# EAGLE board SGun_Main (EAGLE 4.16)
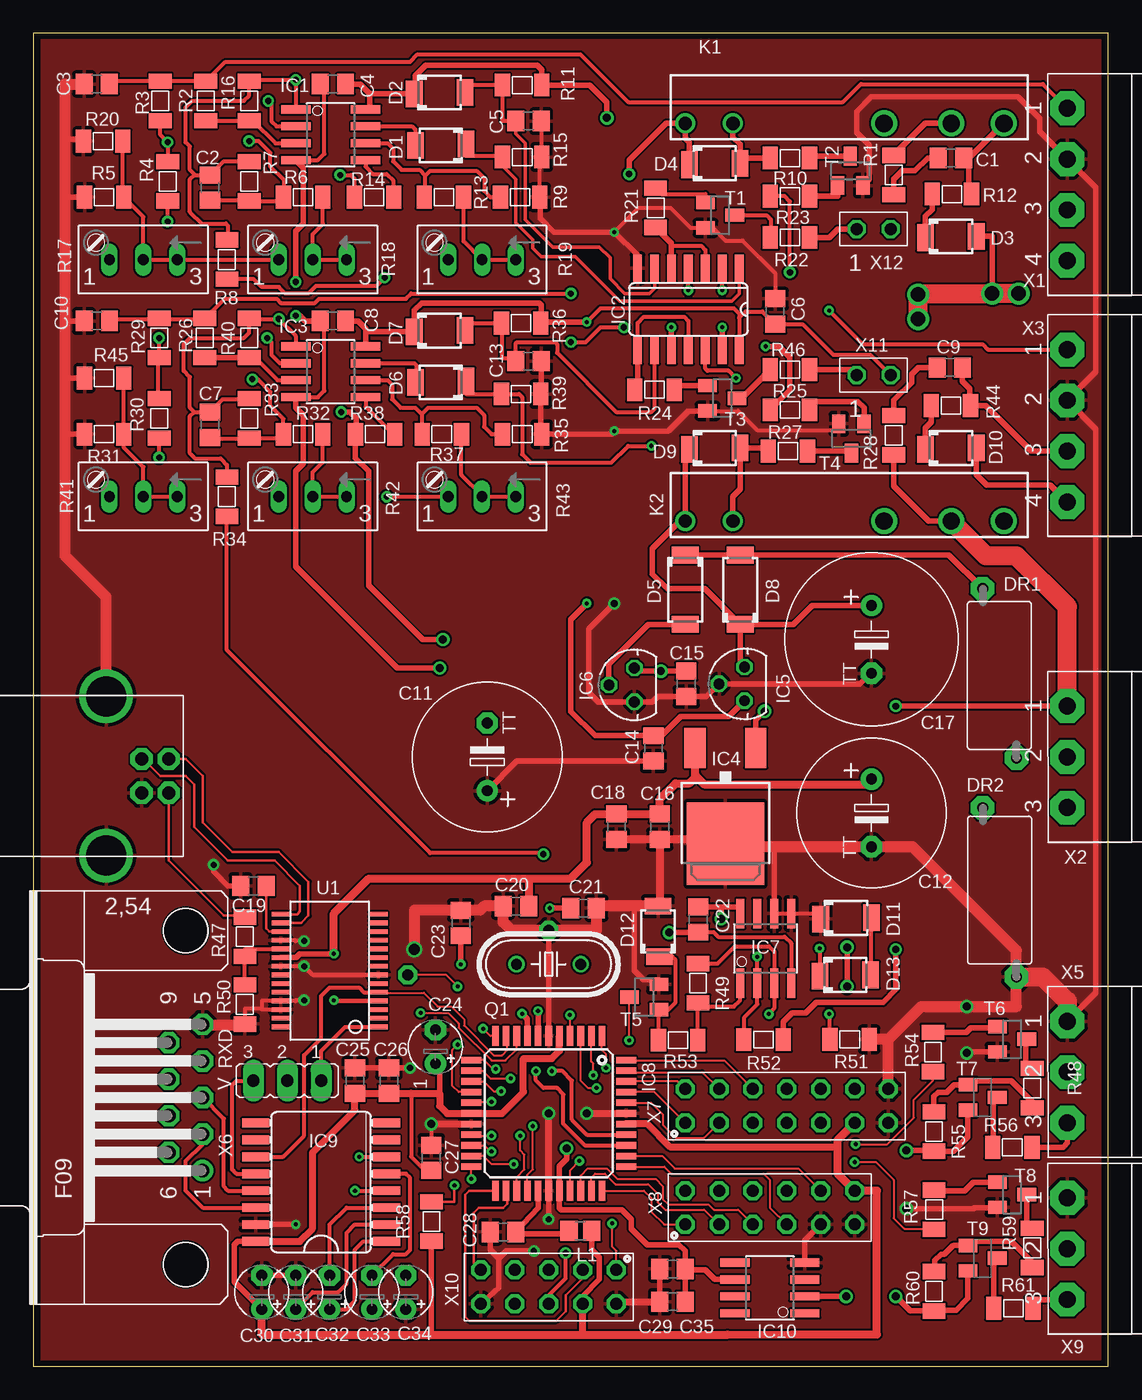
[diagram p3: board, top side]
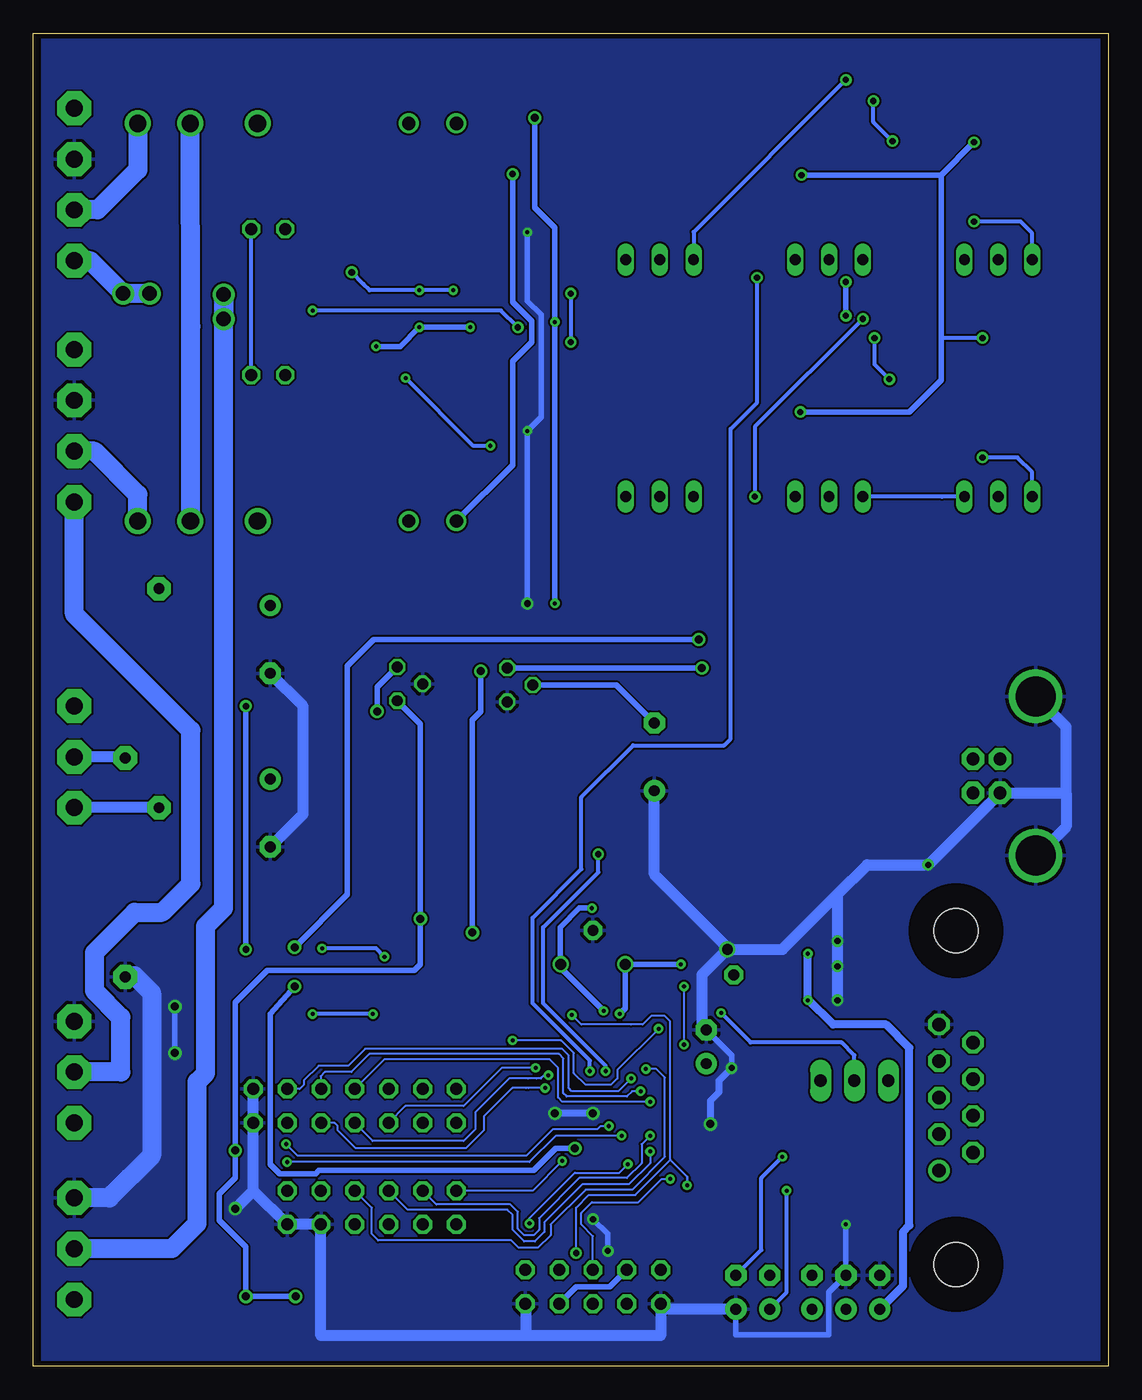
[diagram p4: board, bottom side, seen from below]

Size 80.62 x 100 mm. Coordinates in mm from the lower left corner, seen from the top.
Outline: 0,0 80.62,0 80.62,100 0,100 0,0
Copper layers (1*16): Top 0.035mm / dielectric 1.5mm / Bottom 0.035mm
Design rules "Q-PCB": minimum track width 6mil, minimum drill 0.3mm, track to track 6mil, track to pad 6mil, pad to pad 6mil, via to via 6mil, smd to smd 6mil, copper to edge 6mil, drill to drill 6mil, minimum pad ring 0.2mm, minimum via ring 0.2mm, stop-mask expansion 4mil, vias tented up to drill 0mil, thermal gap 10mil

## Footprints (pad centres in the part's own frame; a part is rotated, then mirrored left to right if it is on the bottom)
0805 = smd 1.27 x 1.524: 1 -0.953,0; 2 0.953,0
TT5D11 = drill 0.813 pad 1.6 round: + 2.54,0 | drill 0.813 pad 1.6 octagon: - -2.54,0
TT5D13 = drill 0.813 pad 1.6 round: + 2.54,0 | drill 0.813 pad 1.6 octagon: - -2.54,0
TT2D4 = drill 0.813 pad 1.6 round: + 1.27,0 | drill 0.813 pad 1.6 octagon: - -1.27,0
DIODE = smd 1.25 x 2: + -1.9,0; - 1.9,0.1
DIODE_SMD_5.0 = smd 1.25 x 2: + -2.6,0; - 2.6,0
DROSSEL1 = drill 0.813 pad 1.778 octagon: 1 -6.35,-1.27; 2 6.35,1.27
PIN1 = drill 0.813 pad 1.422 octagon: 1 0,0
SO08 = smd 0.61 x 2.21: 1 -1.905,-2.616; 2 -0.635,-2.616; 3 0.635,-2.616; 4 1.905,-2.616; 5 1.905,2.616; 6 0.635,2.616; 7 -0.635,2.616; 8 -1.905,2.616
SO14 = smd 0.66 x 2.032: 1 -3.81,-3.073; 2 -2.54,-3.073; 3 -1.27,-3.073; 4 0,-3.073; 5 1.27,-3.073; 6 2.54,-3.073; 7 3.81,-3.073; 8 3.81,3.073; 9 2.54,3.073; 10 1.27,3.073; 11 0,3.073; 12 -1.27,3.073; 13 -2.54,3.073; 14 -3.81,3.073
DPACK = smd 1.6 x 3: 1 -2.28,-4.8; 3 2.28,-4.8 | smd 5.8 x 6.2: 2 0,2.38
78LXX = drill 0.813 octagon: GND 0,1.905; IN 1.27,0; OUT -1.27,0
79LXX = drill 0.813 octagon: GND -1.27,0; IN 0,1.905; OUT 1.27,0
TQFP44 = smd 1.5 x 0.5: 1 -5.8,4; 2 -5.8,3.2; 3 -5.8,2.4; 4 -5.8,1.6; 5 -5.8,0.8; 6 -5.8,0; 7 -5.8,-0.8; 8 -5.8,-1.6; 9 -5.8,-2.4; 10 -5.8,-3.2; 11 -5.8,-4; 23 5.8,-4; 24 5.8,-3.2; 25 5.8,-2.4; 26 5.8,-1.6; 27 5.8,-0.8; 28 5.8,0; 29 5.8,0.8; 30 5.8,1.6; 31 5.8,2.4; 32 5.8,3.2; 33 5.8,4 | smd 0.5 x 1.5: 12 -4,-5.8; 13 -3.2,-5.8; 14 -2.4,-5.8; 15 -1.6,-5.8; 16 -0.8,-5.8; 17 0,-5.8; 18 0.8,-5.8; 19 1.6,-5.8; 20 2.4,-5.8; 21 3.2,-5.8; 22 4,-5.8; 34 4,5.8; 35 3.2,5.8; 36 2.4,5.8; 37 1.6,5.8; 38 0.8,5.8; 39 0,5.8; 40 -0.8,5.8; 41 -1.6,5.8; 42 -2.4,5.8; 43 -3.2,5.8; 44 -4,5.8
SO16L = smd 0.66 x 2.032: 1 -4.445,-4.902; 2 -3.175,-4.902; 3 -1.905,-4.902; 4 -0.635,-4.902; 5 0.635,-4.902; 6 1.905,-4.902; 7 3.175,-4.902; 8 4.445,-4.902; 9 4.445,4.902; 10 3.175,4.902; 11 1.905,4.902; 12 0.635,4.902; 13 -0.635,4.902; 14 -1.905,4.902; 15 -3.175,4.902; 16 -4.445,4.902
PE-FORM-D = drill 1 round: 1 -12.7,-1.2; 2 -9.12,-1.2 | drill 1.3 round: COM 7.26,-1.2; NC 2.22,-1.2; NO 11.2,-1.2
SM-0805 = smd 1.3 x 1.5: 1 -0.85,0; 2 0.85,0
HC49U-V = drill 0.813 round: 1 -2.413,0; 2 2.413,0
R-SMD-1206 = smd 1.143 x 1.702: 1 -1.473,0; 2 1.473,0
S64W = drill 0.813 long: A 2.54,1.27; E -2.54,1.27; S 0,1.27
JP3Y = drill 0.914 pad 1.587 long: 1 -2.54,0; 2 0,0; 3 2.54,0
SOT23 = smd 1 x 1.4: 1 -0.95,-1.1; 2 0.95,-1.1; 3 0,1.1
SOT23-BEC = smd 1 x 1.4: B -0.95,-1.1; C 0,1.1; E 0.95,-1.1
SSOP28DB = smd 0.348 x 1.397: 1 -4.225,-3.656; 2 -3.575,-3.656; 3 -2.925,-3.656; 4 -2.275,-3.656; 5 -1.625,-3.656; 6 -0.975,-3.656; 7 -0.325,-3.656; 8 0.325,-3.656; 9 0.975,-3.656; 10 1.625,-3.656; 11 2.275,-3.656; 12 2.925,-3.656; 13 3.575,-3.656; 14 4.225,-3.656; 15 4.225,3.656; 16 3.575,3.656; 17 2.925,3.656; 18 2.275,3.656; 19 1.625,3.656; 20 0.975,3.656; 21 0.325,3.656; 22 -0.325,3.656; 23 -0.975,3.656; 24 -1.625,3.656; 25 -2.275,3.656; 26 -2.925,3.656; 27 -3.575,3.656; 28 -4.225,3.656
G381-4 = drill 1.27 pad 2.54 octagon: 1 -5.08,-2.54; 2 -1.27,-2.54; 3 2.54,-2.54; 4 6.35,-2.54
G381-3 = drill 1.27 pad 2.54 octagon: 1 -5.08,-2.54; 2 -1.27,-2.54; 3 2.54,-2.54
USB-B = drill 0.96 pad 1.676 octagon: 1 1.27,3.81; 2 -1.27,3.81; 3 -1.27,1.778; 4 1.27,1.778 | drill 3 pad 4 round: G1 -5.969,-0.889; G2 5.969,-0.889
F09H = drill 1.016 pad 1.6 round: 1 -5.486,-1.27 | drill 1.016 pad 1.6 octagon: 2 -2.743,-1.27; 3 0,-1.27; 4 2.743,-1.27; 5 5.486,-1.27; 6 -4.115,1.27; 7 -1.372,1.27; 8 1.372,1.27; 9 4.115,1.27 | hole 3.302: -12.522,0; 12.522,0
ST14-2.54D = drill 0.9 pad 1.422 octagon: 1 -7.62,-1.27; 2 -7.62,1.27; 3 -5.08,-1.27; 4 -5.08,1.27; 5 -2.54,-1.27; 6 -2.54,1.27; 7 0,-1.27; 8 0,1.27; 9 2.54,-1.27; 10 2.54,1.27; 11 5.08,-1.27; 12 5.08,1.27; 13 7.62,-1.27; 14 7.62,1.27
ST12-2.54D = drill 0.9 pad 1.422 octagon: 1 -6.35,-1.27; 2 -6.35,1.27; 3 -3.81,-1.27; 4 -3.81,1.27; 5 -1.27,-1.27; 6 -1.27,1.27; 7 1.27,-1.27; 8 1.27,1.27; 9 3.81,-1.27; 10 3.81,1.27; 11 6.35,-1.27; 12 6.35,1.27
ST10-2.54D = drill 0.9 pad 1.422 octagon: 1 -5.08,-1.27; 2 -5.08,1.27; 3 -2.54,-1.27; 4 -2.54,1.27; 5 0,-1.27; 6 0,1.27; 7 2.54,-1.27; 8 2.54,1.27; 9 5.08,-1.27; 10 5.08,1.27
ST2-254 = drill 0.9 octagon: 1 -1.27,0; 2 1.27,0

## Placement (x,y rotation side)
C1  100n  [0805]  68.81,90.64 180 top
C2  100n  [0805]  13.25,88.42 90 top
C3  100n  [0805]  4.76,96.2 180 top
C4  100n  [0805]  22.46,96.2 180 top
C5  220n  [0805]  37.14,93.42 180 top
C6  10n  [0805]  55.64,79.13 90 top
C7  100n  [0805]  13.25,70.64 90 top
C8  100n  [0805]  22.46,78.42 180 top
C9  100n  [0805]  68.73,74.92 180 top
C10  100n  [0805]  4.76,78.42 180 top
C11  220u  [TT5D11]  34.05,45.71 270 top
C12  220u  [TT5D11]  62.86,41.51 90 top
C13  220n  [0805]  37.14,75.4 180 top
C14  100n  [0805]  46.51,46.35 90 top
C15  100n  [0805]  48.97,51.19 270 top
C16  100n  [0805]  46.98,40.47 90 top
C17  470u  [TT5D13]  62.86,54.52 90 top
C18  22p  [0805]  43.73,40.47 90 top
C19  100n  [0805]  16.5,36.03 180 top
C20  100n  [0805]  36.19,34.52 0 top
C21  22pF  [0805]  41.27,34.36 180 top
C22  100n  [0805]  49.87,33.52 270 top
C23  22pF  [0805]  32.06,33.25 270 top
C24  1uF  [TT2D4]  30.16,23.96 270 top
C25  100n  [0805]  24.12,21.42 90 top
C26  100n  [0805]  26.66,21.42 90 top
C27  100n  [0805]  29.84,15.63 270 top
C28  100n  [0805]  35.24,10.07 180 top
C29  100n  [0805]  47.94,7.3 0 top
C30  1uF  [TT2D4]  17.14,5.55 270 top
C31  1uF  [TT2D4]  19.68,5.55 270 top
C32  1uF  [TT2D4]  22.22,5.55 270 top
C33  1uF  [TT2D4]  25.39,5.55 270 top
C34  1uF  [TT2D4]  27.93,5.55 270 top
C35  100n  [0805]  47.94,4.84 0 top
D1  1N4148  [DIODE]  30.55,91.59 0 top
D2  1N4148  [DIODE]  30.47,95.56 180 top
D3  1N4148  [DIODE]  68.81,84.77 180 top
D4  BAV103  [DIODE]  51.11,90.24 180 top
D5  1N4002  [DIODE_SMD_5.0]  48.89,58.26 90 top
D6  1N4148  [DIODE]  30.55,73.81 0 top
D7  1N4148  [DIODE]  30.47,77.7 180 top
D8  1N4002  [DIODE_SMD_5.0]  53.02,58.26 270 top
D9  BAV103  [DIODE]  51.11,68.89 180 top
D10  1N4148  [DIODE]  68.81,68.89 180 top
D11  ZF4,3  [DIODE]  60.96,33.64 180 top
D12  1N4148  [DIODE]  46.85,32.62 270 top
D13  ZF4,3  [DIODE]  60.9,29.36 180 top
DR1  [DROSSEL1]  72.46,51.98 90 top
DR2  [DROSSEL1]  72.46,35.55 270 top
E1  0VQuarz  [PIN1]  38.65,32.7 0 top
E2  Messpkt.  [PIN1]  28.09,29.36 0 top
IC1  LM358  [SO08]  22.3,92.39 270 top
IC2  4093D  [SO14]  49.13,79.29 180 top
IC3  LM358  [SO08]  22.3,74.61 270 top
IC4  7805  [DPACK]  51.91,41.59 180 top
IC5  78L09  [78LXX]  53.34,51.19 90 top
IC6  79L09  [79LXX]  45.08,51.11 90 top
IC7  LM358  [SO08]  54.93,31.34 0 top
IC8  MEGA16-A  [TQFP44]  38.65,18.96 270 top
IC9  MAX232ECWE  [SO16L]  21.58,13.81 90 top
IC10  [SO08]  55.24,5.87 90 top
K1  RELAIS  [PE-FORM-D]  61.59,94.45 0 top
K2  RELAIS  [PE-FORM-D]  61.59,64.6 0 top
L1  10uH  [SM-0805]  41.03,10.15 180 top
Q1  16MHz  [HC49U-V]  38.65,30.16 180 top
R1  100R  [R-SMD-1206]  64.53,89.37 270 top
R2  10K  [R-SMD-1206]  12.93,94.93 90 top
R3  1K5  [R-SMD-1206]  9.52,94.93 90 top
R4  10K  [R-SMD-1206]  10.08,88.89 270 top
R5  4K75  [R-SMD-1206]  5.31,87.7 180 top
R6  6K81  [R-SMD-1206]  20.24,87.7 0 top
R7  511K  [R-SMD-1206]  16.19,88.89 270 top
R8  10K  [R-SMD-1206]  14.52,83.02 90 top
R9  100K  [R-SMD-1206]  36.51,87.7 0 top
R10  330R  [R-SMD-1206]  56.75,90.64 180 top
R11  100K  [R-SMD-1206]  36.67,96.12 180 top
R12  4K75  [R-SMD-1206]  68.89,87.94 0 top
R13  10K  [R-SMD-1206]  30.79,87.7 180 top
R14  10K  [R-SMD-1206]  25.55,87.7 0 top
R15  100K  [R-SMD-1206]  36.67,90.72 0 top
R16  10K  [R-SMD-1206]  16.19,94.93 270 top
R17  1K  [S64W]  8.25,84.29 180 top
R18  2K  [S64W]  20.95,84.29 180 top
R19  10K  [S64W]  33.65,84.29 180 top
R20  200R  [R-SMD-1206]  5.23,91.91 180 top
R21  22K1  [R-SMD-1206]  46.67,86.91 270 top
R22  680R  [R-SMD-1206]  56.75,84.69 180 top
R23  10K  [R-SMD-1206]  56.75,87.78 0 top
R24  22K1  [R-SMD-1206]  46.59,73.26 180 top
R25  10K  [R-SMD-1206]  56.75,71.75 0 top
R26  10K  [R-SMD-1206]  12.85,77.15 90 top
R27  330R  [R-SMD-1206]  56.59,68.65 180 top
R28  100R  [R-SMD-1206]  64.53,69.84 90 top
R29  1K5  [R-SMD-1206]  9.44,77.15 90 top
R30  10K  [R-SMD-1206]  9.44,71.11 270 top
R31  4K75  [R-SMD-1206]  5.31,69.92 180 top
R32  6K81  [R-SMD-1206]  20.24,69.92 0 top
R33  511K  [R-SMD-1206]  16.19,71.11 270 top
R34  10K  [R-SMD-1206]  14.52,65.24 90 top
R35  100K  [R-SMD-1206]  36.67,69.92 0 top
R36  100K  [R-SMD-1206]  36.59,78.26 180 top
R37  10K  [R-SMD-1206]  30.63,69.92 180 top
R38  10K  [R-SMD-1206]  25.63,69.92 0 top
R39  100K  [R-SMD-1206]  36.59,72.94 0 top
R40  10K  [R-SMD-1206]  16.19,77.15 270 top
R41  1K  [S64W]  8.25,66.51 180 top
R42  2K  [S64W]  20.95,66.51 180 top
R43  10K  [S64W]  33.65,66.51 180 top
R44  4K75  [R-SMD-1206]  68.81,72.07 0 top
R45  200R  [R-SMD-1206]  5.31,74.13 180 top
R46  680R  [R-SMD-1206]  56.75,74.77 180 top
R47  4K7  [R-SMD-1206]  15.87,32.22 90 top
R48  15K  [R-SMD-1206]  74.91,20.86 270 top
R49  100K  [R-SMD-1206]  49.85,28.73 270 top
R50  10K  [R-SMD-1206]  15.87,27.14 270 top
R51  1K  [R-SMD-1206]  61.23,24.52 0 top
R52  1K5  [R-SMD-1206]  54.76,24.5 180 top
R53  47K  [R-SMD-1206]  48.36,24.46 180 top
R54  100K  [R-SMD-1206]  67.47,23.57 90 top
R55  47K  [R-SMD-1206]  67.55,17.6 270 top
R56  360R  [R-SMD-1206]  73.42,16.41 0 top
R57  100K  [R-SMD-1206]  67.55,11.75 90 top
R58  10K  [R-SMD-1206]  29.86,10.86 90 top
R59  15K  [R-SMD-1206]  74.91,8.88 270 top
R60  47K  [R-SMD-1206]  67.55,5.62 270 top
R61  360R  [R-SMD-1206]  73.5,4.35 0 top
RXD  JP1  [JP3Y]  19.04,21.42 180 top
T1  BC846  [SOT23]  51.51,86.35 270 top
T2  BC846  [SOT23]  61.27,89.69 0 top
T3  BC846  [SOT23]  51.67,72.62 270 top
T4  BC846  [SOT23]  61.35,69.61 180 top
T5  BC846  [SOT23]  45.82,27.69 90 top
T6  BC846  [SOT23]  73.41,24.53 270 top
T7  BC856  [SOT23-BEC]  71.19,20.17 270 top
T8  BC846  [SOT23]  73.41,12.86 270 top
T9  BC856  [SOT23-BEC]  71.19,8.1 270 top
U1  [SSOP28DB]  22.22,29.68 90 top
X1  [G381-4]  80.08,89.29 270 top
X2  G381-3  [G381-3]  80.08,44.44 270 top
X3  [G381-4]  80.08,71.19 270 top
X4  USB-B  [USB-B]  6.34,44.28 270 top
X5  G381-3  [G381-3]  80.09,20.8 270 top
X6  F09H  [F09H]  11.42,20.15 90 top
X7  [ST14-2.54D]  56.51,19.52 0 top
X8  [ST12-2.54D]  55.24,11.9 0 top
X9  G381-3  [G381-3]  80.09,7.54 270 top
X10  ST10-2.54D  [ST10-2.54D]  38.65,5.95 180 top
X11  ST2-254  [ST2-254]  63.02,74.37 0 top
X12  ST2-254  [ST2-254]  63.02,85.32 0 top

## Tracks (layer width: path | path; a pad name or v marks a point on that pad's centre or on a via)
0_DETEC  (via drill 0.3)
  Top 0.152: IC8.11 34.28,24.76 v33.73,25.31 | T5.3 44.69,27.69 44.68,27.7 v44.68,24.44
  Bottom 0.152: v33.73,25.31 36.82,22.22 36.82,21.58 37.3,21.11 39.21,21.11 40.08,21.98 40.08,23.49 41.03,24.44 v44.68,24.44
+5V  (via drill 0.46, 0.6)
  Top 0.305: R3.1 9.52,92.39 v10.08,91.83 10.08,90.4 10.07,90.4 R4.1 | R14.1 24.08,89.1 23.81,89.37 v23.01,89.37 | v9.44,77.15 R29.1 9.36,75.59 9.36,72.54 9.39,72.54 R30.1
  Top 0.406: IC8.29 39.45,11.89 39.6,11.74 44.13,11.74 44.84,11.03 44.84,10.31 46.03,9.12 48.41,9.12 48.89,8.65 C29.2 48.89,7.22 | C35.2 48.89,7.22 | IC10.6 51.11,6.5 50.4,7.22 48.89,7.22 | 39.44,13.17 39.44,15 40,15.55 v40,16.34 | v61.03,28.49 v61.03,31.43 | v23.09,71.59 23.73,71.59 24.2,71.11 24.2,69.92 R38.1 24.16,68.14 25.16,67.14 25.16,58.57 29.2,54.52 v30.71,54.52
  Top 0.508: IC8.29 39.44,13.17
  Bottom 0.305: v9.44,77.15 12.54,77.15 | 12.54,89.37
  Bottom 0.406: v40,16.34 41.43,16.34 43.1,14.68 59.21,14.68 59.45,14.44 62.15,14.44 62.86,15.15 62.86,25.23 | v61.03,31.43 57.07,35.39 57.07,52.54 55.08,54.52 v30.71,54.52 | 62.86,25.23 | v61.03,28.49 62.86,26.43 62.86,25.23 | 12.54,89.37 v23.01,89.37 | 12.54,89.37 v10.08,91.83 | v23.09,71.59 14.92,71.59 12.54,73.97 12.54,77.15 12.54,89.37
+9V  (via drill 0.3, 0.6)
  Top 0.305: IC7.8 53.02,34.47 | 70.08,7.14 T9.E | 52.94,78.65 52.94,78.97 52.54,79.37 42.78,79.37 42.54,79.37 v41.51,78.34 | 52.94,78.65 IC2.14 | 52.94,78.65 53.41,79.13 54.68,79.13 C6.1 | C6.1 | C6.1 | C6.1 57.7,78.18 60,75.88 62.78,75.88 X11.2 | X11.2 | X11.2 | 28.57,95.48 D2.- | 25.24,94.61 IC1.8
  Top 0.406: 51.59,34.47 C22.1 | 51.59,34.47 53.02,34.47 | IC10.2 v60.95,5.23 | R60.2 65.77,4.15 v64.69,5.23 | T9.E 70.09,5.08 69.21,4.2 67.7,4.2 | R55.2 69,16.13 70.08,17.22 70.08,19.28 70.09,19.28 T7.E | v65.48,16.19 67.46,16.19 | v51.59,33.57 51.59,34.47 | IC5.OUT 52.14,48.73 48.57,48.73 47.14,47.3 C14.2 42.14,47.3 40.32,49.13 40.32,56.03 v41.51,57.22 | C4.1 24.52,96.2 25.24,95.48 | 28.57,95.48 25.24,95.48 | 25.24,95.48 25.24,94.61 | v43.02,93.66 43.02,94.85 41.75,96.12 R11.1 38.14,97.26 37.78,97.62 29.44,97.62 28.65,96.83 28.65,95.54 D2.- | C8.1 24.36,78.42 24.92,77.86 24.92,77.62 | IC3.8 | IC3.8 | 24.92,77.62 IC3.8 | 24.92,77.62 24.94,77.6 D7.- 28.57,79.22 29.13,79.77 37.94,79.77 38.09,79.61 38.09,78.42 38.17,78.34 | 38.17,78.34 38.09,78.26 R36.1 | v41.51,78.34 38.17,78.34
  Top 0.508: R60.2 67.6,4.15 67.62,4.12 67.7,4.2 | R55.2 67.55,16.11 67.54,16.11 67.46,16.19 | IC10.2
  Bottom 0.305: X11.2 | X11.2 | X11.2 X12.2 | X11.2
  Bottom 0.406: v60.95,5.23 v64.69,5.23 64.69,8.96 66.67,10.95 66.67,12.93 65.48,14.12 v65.48,16.19 65.48,27.3 63.1,29.68 52.06,29.68 51.59,30.16 v51.59,33.57 51.59,48.17 IC5.OUT | v41.51,57.22 v41.51,78.34 41.51,85.4 43.02,86.91 v43.02,93.66
+LON1
  Top 0.406: R12.1 67.42,86.78 66.91,86.27 66.91,84.77 66.91,84.76 D3.-
+LON2
  Top 0.406: R44.1 67.34,70.83 66.91,70.4 66.91,68.89 D10.-
-9V  (via drill 0.46, 0.6)
  Top 0.305: C22.2 51.01,32.56 51.35,32.22 56.35,32.22 56.83,31.74 56.83,28.81 56.83,28.8 IC7.4 | C4.2 21.82,95.88 21.82,90.96 21.35,90.48 IC1.4 | IC1.4 19.6,90.48 | IC1.4 | C8.2 21.82,78.42 21.82,73.18 21.35,72.7 IC3.4 | IC3.4 | IC3.4
  Top 0.406: C22.2 49.84,32.54 v47.7,32.54 | C15.1 | C15.1 v47.06,52.14 45.32,52.14 IC6.OUT | IC1.4 20.24,89.93 20.24,85.72 19.68,85.16 v19.68,81.35 | IC1.4 | v19.68,78.81 20,78.81 20.39,78.42 C8.2 | IC3.4 19.68,71.91 20.24,71.35 20.24,67.7 19.68,67.14 19.68,60 27.3,52.38 28.89,52.38 | v30.47,52.38 28.89,52.38 | 28.89,52.38
  Bottom 0.406: v47.7,32.54 47.7,48.49 47.06,49.13 v47.06,52.14 | IC6.OUT v30.47,52.38 | v30.47,52.38 | v19.68,78.81 v19.68,81.35
-LON1  (via drill 1.1)
  Top 0.406: D3.+ 71.91,84.77 v71.91,80.48
  Top 1.422: v71.91,80.48 | v73.89,80.48 v71.91,80.48 | v66.35,78.58 66.35,80.48 v71.91,80.48
  Bottom 1.422: X9.2 70.24,8.81 68.34,10.71 68.34,21.35 67.7,21.98 67.7,33.01 66.35,34.36 v66.35,80.4 | X1.4 76.35,82.94 v73.89,80.48 v71.91,80.48 | v66.35,80.4 66.35,80.48 | v66.35,80.4 v66.35,78.58
-LON2
  Top 0.406: D10.+ 70.71,66.91 71.51,66.11 76.27,66.11 X3.4
  Bottom 1.422: X5.2 74.05,22.07 74.05,26.19 76.04,28.17 76.04,31.03 | X3.4 77.54,56.43 68.81,47.7 68.81,36.19 70.96,34.05 73.02,34.05 76.04,31.03 | 76.04,31.03
/RESET  (via drill 0.3, 0.46)
  Top 0.152: IC8.4 40.24,24.76 v40.24,26.35
  Top 0.203: R58.2 31.59,12.33 v31.59,13.57
  Top 0.305: X10.6 38.65,5.31 39.92,6.58 v39.92,8.49
  Bottom 0.152: v39.92,8.49 39.92,11.9 38.97,12.85 35.48,12.85 33.89,14.44 | 33.89,14.44 | 33.89,14.44 32.86,15.47 32.86,18.57 | 32.86,18.57 | 32.86,18.57 32.86,25.87 33.25,26.27 34.28,26.27 34.92,25.63 35.79,25.63 39.52,25.63 v40.24,26.35
  Bottom 0.203: v31.59,13.57 31.59,14.2 32.86,15.47
D0
  Top 0.152: IC8.40 46.34,19.76 47.22,18.88 47.22,18.09 48.18,17.14 50.32,17.14 X7.3 | X7.3 | X7.3
D1
  Top 0.152: X7.1 | X7.1 | IC8.41 46.58,20.56 X7.1
D2
  Top 0.152: X7.2 | X7.2 | IC8.42 48.32,21.36 X7.2
D3
  Top 0.152: 44.48,22.14 IC8.43 44.45,22.13 44.52,22.06 50.16,22.06 X7.4 | X7.4 | X7.4
D4
  Top 0.152: IC8.44 44.48,22.93 51.83,22.93 X7.6 | X7.6 | X7.6
D5  (via drill 0.3)
  Top 0.152: IC8.1 42.65,24.68 42.55,24.68 42.55,24.43 42.62,24.36 42.62,23.73 42.95,23.4 v42.95,22.38
  Bottom 0.152: v42.95,22.38 45.49,22.38 48.35,19.53 52.72,19.53 53.99,18.26 X7.5
D6  (via drill 0.3)
  Top 0.152: IC8.2 41.84,22.86 42,22.7 v42,21.83
  Bottom 0.152: v42,21.83 42.31,21.83 42.55,21.59 42.87,21.59 43.51,21.59 44.94,21.59 47.48,19.05 47.48,17.78 48.35,16.91 55.18,16.91 56.52,18.25 | 56.52,18.25 56.53,18.26 | 56.52,18.25 X7.7
D7  (via drill 0.3)
  Top 0.152: IC8.3 41.05,21.41 41.59,20.87 42.22,20.87 42.23,20.88 v42.23,20.88
  Bottom 0.152: v42.23,20.88 43.51,20.88 43.66,20.88 44.7,20.88 46.84,18.73 46.84,17.7 48.19,16.35 56.45,16.35 57.8,17.7 57.8,18.02 58.04,18.26 58.9,18.26 | 58.9,18.26 58.91,18.26 | 58.9,18.26 X7.9
EN1  (via drill 0.3)
  Top 0.152: IC8.16 32.92,19.84 v34.36,19.84
  Bottom 0.152: v34.36,19.84 35.4,19.84 36.03,19.84 40.79,19.84 40.95,19.84 41.27,20.15 41.27,22.38 41.91,23.02 54.3,23.02 56.53,20.8 X7.8
EN2  (via drill 0.3)
  Top 0.152: IC8.15 31.89,20.56 31.43,21.03 31.43,23.73 v31.82,24.12 | E2.1 30.95,29.36 v31.82,28.49
  Bottom 0.152: v31.82,24.12 v31.82,28.49
GND  (via drill 0.3, 0.46, 0.5, 0.6, 0.8)
  Top 0.203: C19.2 15.55,35.39 | U1.18 18.46,31.95 | 18.67,27.4 18.73,27.46 | 18.73,30 18.72,30 U1.21
  Top 0.305: 18.67,27.4 19.68,27.4 19.68,27.46 v20.31,27.46 | 18.67,27.4 U1.25 | 18.72,30 19.68,30 v20.31,30 | U1.18 19.63,31.95 19.68,31.9 v20.31,31.9 | 18.67,27.4 17.14,27.4 17.14,26.82 | 15.87,25.55 R50.2 15.87,26.82 17.14,26.82 | U1.26 17.14,26.75 17.14,26.82 | 29.84,18.25 | v29.84,18.17 29.84,18.25 | 29.84,18.25 C27.1 | 29.84,18.25 | IC7.5 59.05,33.96 D11.- | IC7.6 IC7.5 | IC7.5 | D11.- 59.05,33.49 | D11.- | T3.2 52.86,71.67 54.29,70.24 60.32,70.24 60.32,70.71 | 60.32,70.71 60.32,70.72 | 60.32,70.71 T4.2 | v43.57,85.08 45.4,86.91 47.78,86.91 49.28,85.4 T1.2 50.95,85.4 51.91,84.45 53.18,84.45 55.64,81.99 55.64,80.16 | 45.32,83.34 IC2.7 | 55.64,80.16 | 55.64,80.16 C6.2 | 3.8,92.07 3.76,92.02 R20.2 | 3.8,92.07 | R5.2 3.84,87.66 3.8,87.62 3.76,87.67 | 38.09,90.72 | 38.09,90.72 R15.2 38.14,93.37 C5.1 | R9.2 37.98,90.61 38.09,90.72 | C5.1
  Top 0.356: U1.7 23.81,29.36 20.95,29.36 v20.31,30
  Top 0.406: v19.68,10.63 IC9.15 | C30.- C31.- | C25.2 C26.2 v28.25,22.38 | v13.52,37.62 13.52,37.11 14.6,36.03 C19.2 | X10.10 34.92,5.87 34.92,8.09 | v38.65,11.03 38.65,13.09 | v37.54,8.65 37.06,8.65 36.35,8.65 35.48,8.65 34.92,8.09 | C28.2 34.28,8.73 34.92,8.09 | X8.9 | IC10.4 57.86,9.44 X8.9 | C35.1 | C35.1 | C35.1 C29.1 | 38.66,32.7 38.66,32.71 | 38.66,32.7 E1.1 | IC8.6 38.66,24.76 38.66,32.7 | D12.+ 45.08,34.52 45.08,29.68 45.79,28.97 46.91,28.97 46.91,28.66 T5.2 | v65.48,11.82 70.48,11.82 70.56,11.9 | T8.2 70.56,11.9 | 70.56,11.9 | T6.2 70.1,23.58 v70,23.49 | IC7.6 55.56,38.97 | C15.2 | C15.2 46.83,50.24 46.43,49.84 IC6.GND | C15.2 50.48,50.24 IC5.GND 61.99,51.19 62.86,52.06 C17.- | X5.1 79.69,28.01 79.69,70.32 X3.2 79.69,74.61 79.69,88.42 X1.2 | 55.56,38.97 | C11.+ | C14.1 36.27,45.4 C11.+ | IC6.GND | IC6.GND | IC6.GND 42.38,49.84 41.67,50.56 41.67,55.32 v43.57,57.22 | v43.57,57.22 | T2.2 62.7,89.07 62.7,91.59 61.75,92.55 61.75,94.13 62.86,95.24 73.81,95.24 75.48,93.58 75.48,92.62 X1.2 | X1.2 | X1.2 | T3.2 49.13,71.67 47.62,70.16 v43.57,70.16 43.33,69.92 R35.2 38.17,69.92 | v43.57,85.08 45.32,83.34 | v43.57,85.08 | v43.57,85.08 41.59,85.08 39.05,85.08 38.02,86.12 | 38.02,86.12 | R9.2 37.98,87.66 38.02,87.62 38.02,86.12 | 38.09,72.94 | 38.09,72.94 R39.2 38.06,70.04 38.17,69.92 | 38.09,72.94 C13.1 | 38.17,69.92 | 2.38,92.07 3.8,92.07 | 2.38,87.7 R5.2 | C10.2 2.38,78.42 | R45.2 2.38,74.13 | R31.2 2.38,69.92
  Top 0.508: 38.65,13.09 IC8.28 v38.65,18.96 | v29.84,18.17 IC8.18 32.86,18.16 | v41.51,18.96 IC8.39 | X10.2 43.89,4.84 C35.1
  Top 0.61: C18.1 C16.1 | IC4.2 | IC4.2 | C16.1 51.91,39.52 IC4.2 | C16.1 | D12.+ 46.98,34.52 C16.1 | IC4.2 51.99,39.21 51.99,38.97
  Top 0.813: X6.5 12.69,25.55 15.76,25.55 R50.2 | v28.57,31.27 28.57,34.2 C23.1 33.49,34.2 33.81,34.52 35.16,34.52 | 35.16,34.52 | 35.16,34.52 C20.1 35.24,33.33 35.87,32.7 E1.1 | 38.66,32.7 42.22,32.7 C21.1 42.38,34.52 D12.+ | X7.14 | 64.13,24.52 R51.2 | X7.14 64.13,24.52 | 64.13,24.52 66.59,26.98 v70,26.98 73.73,26.98 DR2.2 73.73,31.19 65.96,38.97 C12.- 55.72,38.97 55.56,38.97 54.52,38.97 51.99,38.97 | X4.G1 5.46,57.71 2.38,60.8 2.38,69.92 2.38,74.13 2.38,78.42 2.38,87.7 2.38,92.07 2.38,96.2 C3.2 | C3.2 | C3.2
  Top 1.422: DR2.2 75.72,29.2 77.55,27.37 77.54,27.37 | 77.54,27.37 77.54,27.38 | X5.1 77.54,27.37
  Bottom 0.406: v19.68,10.63 C31.- 20.95,5.55 20.95,2.38 27.93,2.38 C34.+ | C24.- 28.25,23.33 v28.25,22.38 | v37.54,8.65 37.54,9.92 v38.65,11.03 | v70,26.98 v70,23.49 | v43.57,85.08 43.57,79.92 42.54,78.89 42.54,71.19 v43.57,70.16 v43.57,57.22
  Bottom 0.508: v29.84,18.17 29.84,19.92 29.2,20.55 29.2,21.42 v28.25,22.38 | v38.65,18.96 v41.51,18.96
  Bottom 0.813: X4.G1 3.17,47.97 3.17,43.02 | 3.17,43.02 3.17,40.48 5.33,38.32 X4.G2 | 3.17,43.02 X4.4 v13.52,37.62 18.09,37.62 20.31,35.39 | v20.31,27.46 v20.31,30 v20.31,31.9 20.31,35.39 | 20.31,35.39 24.44,31.27 v28.57,31.27 | v28.57,31.27 30.47,29.36 30.47,25.23 C24.- | C34.+ 33.57,4.28 X10.10 33.57,2.3 43.65,2.3 | X10.2 43.65,4.68 43.65,2.3 | 43.65,2.3 59.05,2.3 X8.9 | X7.13 | X7.13 X7.14 | X7.13 | X8.11 | 64.13,13.17 X7.13 | X8.11 64.13,13.17 | X8.9 | X8.11 | X8.9 X8.11 | X8.11 | 64.13,13.17 v65.48,11.82 | C17.- 60.4,49.52 60.4,41.43 C12.- | v28.57,31.27 28.49,31.35 34.05,36.9 C11.+
  Bottom 1.422: X9.1 74.92,12.62 71.75,15.79 71.75,28.01 73.02,29.28 73.73,29.28 DR2.2
  pour Bottom: 0.63,99.53 80,99.53 80,0.47 0.63,0.47
  pour Top: 0.63,99.53 80,99.53 80,0.47 0.63,0.47
IC8
  Top 0.305: IC2.5 47.86,84.05 50.08,84.05 50.4,83.73 50.4,82.39 | 50.4,82.39 | 50.4,82.39 IC2.3
  Top 0.406: IC2.5 | R21.2 47.86,84.25 IC2.5
N$1  (via drill 0.3)
  Top 0.305: R52.2 53.29,24.55 53.33,24.6 53.33,26.19 54.29,27.15 IC7.2 v54.29,30.71 | D13.- 59,31.32 v58.97,31.35
  Bottom 0.305: v58.97,31.35 54.92,31.35 v54.29,30.71
N$2
  Top 0.203: U1.16 20.08,33.25 20.63,33.81 20.63,36.35 18.41,38.57 14.92,38.57 12.69,40.79 12.69,44.28 11.42,45.55 X4.2
N$3
  Top 0.305: D13.+ 62.78,29.36 62.86,29.44 D11.+
N$4  (via drill 0.3)
  Top 0.305: R49.1 51.32,30.21 52.62,31.51 55.16,31.51 55.56,31.11 IC7.3 55.56,26.83 v55.16,26.43 | R51.1 59.75,24.53 59.68,24.6 v59.68,26.43
  Bottom 0.305: v55.16,26.43 v59.68,26.43
N$5
  Top 0.305: 49.88,27.26 49.92,27.3 | 49.88,27.26 R49.2 50.13,26.98 52.54,26.98 53.02,27.46 IC7.1 | R53.1 49.83,27.21 49.88,27.26
N$6
  Top 0.203: X4.3 8.25,45.55 9.52,44.28 11.42,44.28 12.06,43.65 12.06,40.48 14.6,37.94 18.09,37.94 20,36.03 20,34.12 19.78,33.91 U1.15 18.63,33.91
N$7
  Top 0.305: IC9.1 24.76,9.36 24.12,8.73 24.12,4.92 23.49,4.28 C32.+
N$8  (via drill 0.3)
  Top 0.305: v24.12,13.17 IC9.4
  Bottom 0.305: v24.12,13.17 24.12,5.55 C33.+
N$9
  Top 0.305: IC9.3 23.49,11.9 22.22,10.63 C32.-
N$10
  Top 0.305: IC9.5 27.93,14.44 28.25,14.12 28.25,8.73 27.93,8.41 26.98,8.41 C33.-
N$11
  Top 0.305: IC9.2 24.12,10.63 23.49,10 23.49,6.18 22.85,5.55 20.95,5.55 C31.+
N$12  (via drill 0.3)
  Top 0.305: v24.44,15.71 IC9.6
  Bottom 0.305: C34.- 26.03,8.73 26.03,14.12 v24.44,15.71
N$13
  Top 0.406: X12.1 60.32,85.32 59.68,84.69 58.18,84.69 | 58.18,84.69 | R22.1 58.18,84.69
N$14
  Top 0.203: C19.1 17.46,32.85 17.71,32.6 U1.17
  Top 0.305: U1.17 18.66,32.6
N$15  (via drill 0.3)
  Top 0.152: IC8.9 36.25,23.79 35.4,22.93 34.36,22.93 31.9,25.39 31.9,25.71 31.11,26.5 v29.05,26.5
  Bottom 0.305: RXD.2 19.04,23.33 20,24.28 26.82,24.28 v29.05,26.5
N$16
  Top 0.305: X6.2 12.69,16.66 11.42,15.39 11.42,13.17 12.69,11.9 IC9.14
N$17
  Top 0.305: X6.3 14.28,18.57 14.28,13.49 14.6,13.17 IC9.13
N$18
  Top 0.305: R13.1 32.27,84.4 R19.S | R19.S | R19.S R19.E | R19.S
N$19
  Top 0.406: C28.1 | IC8.27 37.85,11.89 C28.1 | C28.1 36.11,9.92 40.18,9.92 L1.2
N$20
  Bottom 0.813: DR1.1 | X2.2 73.81,45.71 DR1.1
N$21
  Bottom 0.813: DR2.1 71.19,41.82 71.27,41.9 X2.3
N$22
  Top 0.406: DR1.2 68.65,60.87 53.02,60.87 | 48.89,60.87 53,60.87
  Top 0.61: 53.02,60.87 D8.+ 53,60.87 | D5.- 48.89,60.87 | D5.-
N$23
  Top 0.305: R50.1 15.87,30.63 | U1.19 15.91,31.3 15.87,31.27 15.87,30.63 | 15.87,30.63 R47.1
N$24
  Top 0.406: R46.1 | X11.1 61.35,74.77 R46.1
N$25  (via drill 0.3)
  Top 0.406: IC8.7 v37.85,26.66 | v38.73,34.36 C21.2
  Bottom 0.406: v37.85,26.66 41.06,29.87 Q1.1 41.11,30.2 41.11,32.93 39.68,34.36 v38.73,34.36
N$26  (via drill 0.3)
  Top 0.406: v32.06,30.16 C23.2 | IC8.8 37.05,26.04 v36.65,26.44
  Top 0.508: v36.65,26.44
  Bottom 0.406: v32.06,30.16 Q1.2 36.24,26.85 v36.65,26.44 | v32.06,30.16 | v36.65,26.44 36.67,26.43 | v36.65,26.44
N$27
  Top 0.203: X4.1 10.15,37.94 14.28,33.81 15.87,33.81 R47.2
N$28
  Top 0.305: IC2.8 45.32,78.26 45.79,78.73 48.81,78.73 49.13,78.42 49.13,76.19 | 49.13,76.19 | 49.13,76.19 IC2.11
  Top 0.406: R24.2 45.32,73.26 IC2.8 | IC2.8
N$29  (via drill 0.3)
  Top 0.406: R25.1 56.75,73.22 56.75,75.72 55.95,76.51 v54.92,76.51 | IC2.10 47.86,76.11 | IC2.10 | IC2.10 v47.86,77.94 | IC2.13 | v51.67,77.94 IC2.13
  Bottom 0.406: v51.67,77.94 | v51.67,77.94 53.1,76.51 v54.92,76.51 | v47.86,77.94 v51.67,77.94
N$36
  Top 0.305: IC1.5 24.91,90.01 25.47,89.45 26.51,89.45 26.98,88.97 26.98,87.7 R14.2
N$37
  Top 0.305: D12.- 47.93,30.71 48.18,30.47 48.18,27.3 47.62,26.74 46.91,26.74 | 46.91,26.74 | 46.91,26.74 T5.1 46.92,24.54 46.85,24.46 | 46.85,24.46 46.83,24.44 | R53.2 46.85,24.46
N$38  (via drill 0.46)
  Top 0.305: R4.2 v10.08,85.88
  Bottom 0.305: v10.08,85.88 6.58,85.88 5.71,85 R17.A | R17.A | R17.A
N$39
  Top 0.406: D5.+ 46.13,55.66 43.17,52.7 IC6.IN | IC6.IN | IC6.IN
  Bottom 0.406: C11.- | IC6.IN 36.9,51.11 C11.-
N$40
  Top 0.305: R20.1 6.71,87.74 6.74,87.7 R5.1 8.25,86.24 R17.S | R17.S | R17.S | R17.E | R17.E | R17.E R18.A | R17.E | R17.S | R17.S | R17.S R17.E | R17.S
N$41
  Top 0.305: R6.2 21.71,85.68 20.95,84.92 20.95,83.1 | 20.95,83.1 | R18.S 20.95,83.1 | R18.E | R18.E | 20.95,83.1 21.03,83.02 R18.E
N$42
  Top 0.305: C3.1 5.95,96.43 9.52,96.43 R3.2 9.55,96.43 12.97,96.43 | 12.97,96.43 13.17,96.43 | 12.97,96.43 R2.2 14.4,97.86 28.25,97.86 28.81,98.42 38.49,98.42 | 38.49,98.42 | 38.49,98.42 41.03,98.42 42.06,97.39 | X1.1 75.72,96.2 62.07,96.2 60.72,94.85 44.6,94.85 42.06,97.39 | 42.06,97.39
N$43  (via drill 0.46)
  Top 0.305: 16.19,87.47 | 16.19,87.47 R7.2 18.52,87.42 18.81,87.7 | C2.1 16.19,87.47 | 16.19,87.47 | IC1.2 18.25,93.02 17.85,93.42 17.85,94.69 v17.62,94.93 | v16.19,91.91 16.9,91.91 17.77,91.04 17.77,90 18.81,88.97 18.81,87.7 | 18.81,87.7 | 18.81,87.7 R6.1
  Bottom 0.305: v17.62,94.93 17.62,93.34 v16.19,91.91
N$44
  Top 0.305: R2.1 16.06,93.45 16.11,93.5 16.15,93.45 R16.2 16.47,93.45 18.17,91.75 19.6,91.75 | 19.6,91.75 | 19.6,91.75 IC1.3
N$45  (via drill 0.46)
  Top 0.305: R7.1 16.19,90.4 14.28,90.4 C2.2 12.14,89.37 12.1,89.41 | R7.1 | 19.6,94.29 | 19.6,94.29 IC1.1 | 19.6,94.29 19.76,94.45 19.68,94.45 v19.68,96.51 16.19,96.51 R16.1 16.19,96.36 16.19,95.32 15.79,94.93 11.9,94.93 11.42,94.45 11.42,91.83 11.74,91.51 11.74,89.77 12.1,89.41 | 14.52,84.53 | 14.52,84.53 R8.2 | 14.52,84.53 14.6,84.61 14.6,85.56 14.44,85.72 12.62,85.72 11.74,86.59 11.74,89.05 12.1,89.41
  Bottom 0.305: R19.A 31.11,85.08 v19.68,96.51
N$46
  Top 0.305: R45.1 6.79,70.2 6.82,70.16 6.79,70.13 R31.1 6.79,68.93 8.25,67.46 8.25,65.32 | 8.25,65.32 | R41.S 8.25,65.32 | R41.S | R41.S | R41.S R41.E | R41.S
  Bottom 0.305: 12.46,65.24 R42.A | R41.E 12.46,65.24 | 12.46,65.24
N$47
  Top 0.305: IC1.6 26.59,91.75 26.98,91.35 26.98,90.4 27.62,89.77 28.97,89.77 29.36,89.37 29.36,89.29 | 29.36,87.7 | 29.36,87.7 R13.2 | 29.36,89.29 29.36,87.7 | R9.1 34.28,87.7 33.81,88.18 33.81,89.13 33.25,89.69 29.76,89.69 29.36,89.29
N$48
  Top 0.305: IC1.7 28.41,93.02 28.65,92.78 D1.+
N$49
  Top 0.254: IC2.1 52.94,80.48 52.38,79.92 43.97,79.92 | 43.97,79.92 40.63,83.26 38.09,83.26 37.46,83.89 37.46,84.53 36.19,85.8 36.19,89.05 35.16,90.08 35.16,90.72 R15.1 | 43.97,79.92 | R15.1
  Top 0.305: R15.1 35.19,90.8 32.45,90.8 D1.-
N$50  (via drill 0.3, 0.5)
  Top 0.305: R23.1 56.35,87.78 56.75,87.39 v56.75,82.07 | IC2.4 49.13,82.39 | IC2.4 | v49.13,80.72 IC2.4 | IC2.2 51.67,82.07 | IC2.2 51.67,82.39 | IC2.2 | v51.67,80.72 IC2.2
  Bottom 0.305: 55.87,81.19 v56.75,82.07 | v49.13,80.72 v51.67,80.72 55.4,80.72 55.87,81.19 | 55.87,81.19
N$52
  Top 0.254: IC2.6 46.59,80.88 46.19,80.48 44.37,80.48 43.25,81.59 43.25,83.18 42.46,83.97 38.97,83.97 36.9,86.04 36.9,91.75 36.19,92.47 C5.2
  Top 0.305: R11.2 35.24,96.12 | D2.+ 32.37,96.12 R11.2 | C5.2 | R11.2 35.19,93.42 C5.2 | C5.2 | C5.2
N$53
  Top 0.406: T2.3 58.38,90.8 R10.1
N$54
  Top 0.305: R21.1 47.11,87.94 50.4,87.94 50.4,87.31 T1.1
  Top 0.406: T1.1 | R21.1 46.63,88.42
N$55
  Top 0.305: T1.3 55,86.35 55.32,86.04 55.32,84.69 | 55.32,84.69 | 55.32,84.69 R22.2
  Top 0.406: 55.24,84.69 | R22.2 55.24,84.69
N$56
  Top 0.406: K1.2 52.47,92.22 53.02,91.67 D4.+ 53.41,90.64 R10.2 | R10.2 55.32,90.64 | R10.2
N$57  (via drill 0.46)
  Top 0.305: R30.2 v9.44,68.18
  Bottom 0.305: v9.44,68.18 6.82,68.18 5.71,67.07 5.71,65.16 | 5.71,65.16 | R41.A 5.71,65.16
N$59
  Top 0.305: R42.S R42.E | R42.S | R32.2 21.71,67.82 20.95,67.07 R42.S | R42.S
N$60  (via drill 0.46)
  Top 0.305: C7.1 13.33,69.61 16.15,69.61 R33.2 18.52,69.64 arc90 18.73,69.84 arc90 18.76,69.88 R32.1 18.76,71.08 17.77,72.07 17.77,73.1 16.82,74.05 v16.43,74.05 | v17.54,77.15 17.85,76.83 17.85,75.88 18.49,75.24 IC3.2 | IC3.2 | IC3.2
  Bottom 0.305: v16.43,74.05 17.54,75.16 v17.54,77.15
N$61  (via drill 0.3, 0.46)
  Top 0.305: X3.1 71.59,76.27 71.19,76.67 62.22,76.67 v59.68,79.21 | v44.29,77.94 42.54,77.94 41.43,76.83 v40.32,76.83 | v40.32,80.48 28.33,80.48 27.93,80.08 21.43,80.08 21.11,79.77 18.57,79.77 18.25,80.08 14.36,80.08 12.93,78.65 12.89,78.65 R26.2 12.85,78.58 9.48,78.58 R29.2 9.44,78.58 5.87,78.58 C10.1
  Bottom 0.305: v59.68,79.21 45.56,79.21 v44.29,77.94 | v40.32,80.48 v40.32,76.83
N$62
  Top 0.305: IC3.3 | R40.2 16.63,75.67 18.33,73.97 IC3.3
  Top 0.406: R26.1 R40.2 | R40.2 | R40.2 16.19,75.64
N$63  (via drill 0.46)
  Top 0.305: IC3.1 19.68,77.31 v18.41,78.58 16.23,78.58 R40.1 16.19,78.58 | IC3.1 | IC3.1 | 12.06,71.59 C7.2 14.2,72.54 16.23,72.54 | 12.06,71.59 11.74,71.91 11.74,74.21 11.27,74.69 11.27,76.67 11.74,77.15 15.79,77.15 16.19,77.54 16.19,78.58 | 16.19,78.58 | R34.2 14.52,67.62 14.04,68.1 12.14,68.1 11.74,68.49 11.74,71.27 12.06,71.59 | 12.06,71.59 | 16.23,72.54 16.27,72.54 | 16.23,72.54 R33.1 | R43.A | v26.51,65.24 R43.A
  Bottom 0.305: v26.51,65.24 26.51,70.48 v18.41,78.58
N$65
  Top 0.305: IC3.6 26.59,73.97 26.9,73.65 26.9,72.54 27.54,71.91 28.65,71.91 29.13,71.43 | 29.13,71.43 29.6,71.91 33.25,71.91 33.81,71.35 33.81,70.48 34.36,69.92 R35.1 | R35.1 | 29.13,69.89 29.13,69.76 | 29.13,69.89 R37.2 | 29.13,71.43 29.13,69.89
N$66
  Top 0.305: R38.2 27.11,69.89 27.06,69.84 24.91,71.99 IC3.5
N$67
  Top 0.305: IC3.7 28.57,75.24 28.73,75.08 28.73,73.73 D6.+
N$68  (via drill 0.3)
  Top 0.305: IC2.12 50.4,74.84 50.56,74.69 52.14,74.69 v52.7,74.13 | R39.1 | D6.- 32.45,72.94 R39.1 | R39.1 36.43,72.94 36.67,72.7 36.67,68.41 37.3,67.78 43.33,67.78 44.6,69.05 v46.35,69.05
  Bottom 0.305: v52.7,74.13 47.62,69.05 v46.35,69.05
N$71
  Top 0.305: IC2.9 46.59,71.83 46.35,71.59 43.73,71.59 39.29,76.03 39.29,76.67 39.13,76.83 36.27,76.83 36.19,76.75 36.19,75.64 36.11,75.64 | D7.+ 32.93,78.26 R36.2 35.11,75.64 36.11,75.64 | 36.11,75.64 C13.2
N$72
  Top 0.406: T3.1 48.38,73.57 R24.1
N$73
  Top 0.406: T3.3 53.13,72.62 R46.2
N$74
  Top 0.406: R27.1 58.02,68.65 | R27.1 | T4.3 61.2,68.65 R27.1
N$75
  Top 0.406: R27.2 54.88,68.89 D9.+ 53.02,65.8 52.46,65.24 52.46,63.41 K2.2
N$76
  Top 0.305: U1.1 23.39,25.45 21.58,23.65 RXD.1
N$77
  Top 0.305: T8.1 | 67.54,13.17 67.55,13.18 R57.2
  Top 0.406: T8.1 70.48,13.81 69.84,13.17 67.54,13.17
N$78
  Top 0.305: 74.91,10.39 74.92,10.39 | R59.1 74.91,10.39 | 74.91,10.39 74.51,10.39
  Top 0.406: 74.51,10.39 T8.3
N$79
  Top 0.305: 67.62,7.22 67.55,7.14 R60.1 | T9.B 70.4,9.36 | 74.85,7.38 74.89,7.38 R59.2
  Top 0.406: T9.B 69.06,9.05 68.97,9.04 68.34,8.41 68.1,8.41 67.62,7.93 | 67.62,7.93 | 67.62,7.22 67.62,7.93 | 70.4,9.36 73.34,9.36 74.85,7.85 74.85,7.38
N$80
  Top 0.305: T9.C 72.29,8.01 72.03,8.01
  Top 0.406: R61.1 72.03,8.01
N$81
  Top 0.305: R61.2 74.98,4.99
  Top 0.406: X9.3 76.52,4.99 74.98,4.99
N$82
  Top 0.406: C1.2 67.07,90.64 66.11,89.69 65.16,89.69 64.53,89.05 64.53,87.94 | 64.53,87.94 | R1.2 64.53,87.94
N$84
  Top 0.406: R54.2 69.97,25.05 70.32,25.39 72.15,25.39 72.23,25.48 T6.1
N$85
  Top 0.406: 74.45,24.53 74.45,24.6 | 74.45,24.53 T6.3 | R48.1 74.45,22.34 74.45,24.53
N$86
  Top 0.406: R48.2 74.91,19.85 73.34,21.42 70.4,21.42 T7.B 69.06,21.11 68.5,20.55 67.86,20.55 67.54,20.23 67.54,19.12 67.55,19.12 R55.1
N$87
  Top 0.406: 71.99,16.38 71.99,16.34 | R56.1 71.99,16.38 | T7.C 71.99,19.86 71.99,16.38
N$88
  Top 0.406: R56.2 74.91,16.42 77.23,16.42 77.54,16.74 X5.3
N$89
  Top 0.406: C9.2 66.35,74.92 65.88,74.45 65.88,73.81 64.53,72.46 R28.2 64.53,71.27
N$90
  Top 0.406: X3.3 74.85,68.65 71.43,72.07 R44.2 70.24,72.07 | C9.1 69.69,73.89 70.24,73.34 70.24,72.07 | 70.24,72.07
  Bottom 1.422: K2.NO 72.79,65.41 76.04,68.65 X3.3
N$91
  Top 0.406: T2.1 60.32,87.78 R23.2
N$92
  Top 0.406: R25.2 58.22,72.38 61.83,72.38 62.3,71.91 T4.1
N$93
  Top 0.305: 33.73,65.24 | 33.73,65.24 R43.S R43.E | R37.1 32.11,66.86 33.73,65.24 | R43.E
PA2
  Top 0.152: X8.10 | X8.10 57.38,14.84 48.1,14.84 47.17,15.76 IC8.35
PA3
  Top 0.152: X8.7 | X8.7 55.24,11.9 55.24,13.96 54.76,14.44 47.86,14.44 47.33,14.96 IC8.34
RD/W  (via drill 0.3)
  Top 0.152: IC8.14 33.79,21.36 34.52,20.63 | 34.52,20.63 34.68,20.63 | 34.52,20.63 v35.08,20.63
  Bottom 0.152: X7.10 59.06,20.79 59.07,20.8 59.07,21.75 58.75,22.07 56.77,22.07 55.42,23.42 41.2,23.42 40.87,23.09 40.87,20.47 40.63,20.23 36.11,20.23 35.71,20.63 v35.08,20.63
RS  (via drill 0.3)
  Top 0.152: IC8.13 33.7,22.16 34.28,21.58 35,21.58 35.32,21.58 v35.79,21.58
  Bottom 0.152: X7.12 61.6,20.79 61.61,20.8 60.66,20.8 60.34,21.11 60.34,21.43 59.23,22.54 57,22.54 55.73,23.81 40.96,23.81 40.48,23.33 40.48,20.87 40.24,20.63 36.75,20.63 v35.79,21.58 | v35.79,21.58
RXD
  Top 0.305: RXD.3 15.23,21.42 14.92,21.11 14.92,14.76 15.23,14.44 IC9.12
SG1  (via drill 0.3)
  Top 0.152: IC8.25 36.25,14.18 36.82,14.76 36.82,15.87 36.51,16.19 v36.51,17.3 | v61.59,15.31 63.18,15.31 64.53,13.96 64.53,11.11 65.32,10.31 67.54,10.31 67.54,10.29 R57.1
  Bottom 0.152: v36.51,17.3 41.43,17.3 43.41,15.31 v61.59,15.31
SG2  (via drill 0.3)
  Top 0.152: 37.06,13.16 IC8.26 37.05,14.35 37.46,14.76 v37.46,18.01 | v61.67,16.66 64.05,16.66 66.03,18.65 66.03,20 67.46,21.42 67.46,22.06 67.47,22.07 R54.1
  Bottom 0.152: v37.46,18.01 38.09,18.01 38.33,17.77 41.67,17.77 43.65,15.79 60.8,15.79 v61.67,16.66
T1
  Top 0.152: IC8.33 42.69,13.16 42.7,13.17 45.79,13.17 46.35,12.61 46.35,11.58 47.3,10.63 X8.1 | X8.1
T2
  Top 0.152: IC8.32 41.85,14.15 42.14,14.44 42.86,14.44 43.65,13.65 46.11,13.65 46.83,12.93 46.83,12.3 47.38,11.74 50.32,11.74 | X8.3 | 50.32,11.74 | 50.32,11.74 X8.3
T3
  Top 0.152: IC8.31 41.05,14.3 41.59,14.84 43.02,14.84 43.81,14.04 46.67,14.04 47.22,13.49 47.22,12.54 47.62,12.14 50.64,12.14 51.03,11.74 52.86,11.74 X8.5 | X8.5
T4  (via drill 0.3)
  Top 0.152: IC8.30 40.25,14.69 v40.95,15.39
  Bottom 0.152: X8.2 | X8.2 43.17,13.17 v40.95,15.39
TCK  (via drill 0.3)
  Top 0.152: IC8.21 33.75,15.76 34.36,15.15 v36.03,15.15 | v43.41,10.71 43.41,8.96 43.73,8.65 X10.1
  Bottom 0.152: v36.03,15.15 36.67,14.52 40,14.52 43.41,11.11 v43.41,10.71
TDI
  Top 0.203: 35.55,13.06 IC8.24 35.53,12.19 35.24,11.9 33.41,11.9 33.01,11.5 33.01,7.77 X10.9
TDO
  Top 0.203: 34.6,12.96 IC8.23 32.69,13.16 32.38,12.85 32.38,3.72 32.7,3.41 39.21,3.41 39.92,4.12 39.92,5.31 41.19,6.58 X10.3
TEMP1  (via drill 0.3, 0.46)
  Top 0.305: IC8.37 41.52,17.36 40.4,18.49 40.4,21.42 39.68,22.14 v38.89,22.14 | R8.1 16.55,81.55 17.14,80.96 18.41,80.96 18.89,80.48 20.63,80.48 21.19,81.04 25.71,81.04 v26.35,81.67
  Bottom 0.305: v38.89,22.14 38.89,22.93 43.17,27.22 43.17,33.65 39.52,37.3 39.52,42.7 35.63,46.59 28.81,46.59 28.33,47.06 28.33,70.32 26.35,72.3 v26.35,81.67
TEMP2  (via drill 0.3, 0.46)
  Top 0.152: 44.43,16.58 IC8.36
  Top 0.305: 44.43,16.58 41.35,16.58 39.76,18.17 39.76,20.39 39.29,20.87 38.25,20.87 37.7,21.42 v37.7,22.14 | R34.1 14.52,53.73 29.76,38.49 38.17,38.49 v38.25,38.41
  Bottom 0.305: v37.7,22.14 37.7,22.54 42.38,27.22 42.38,32.93 38.25,37.06 v38.25,38.41
TMS  (via drill 0.3)
  Top 0.152: IC8.22 v32.85,14.05 v32.86,14.04
  Bottom 0.152: v32.86,14.04 33.49,14.04 35.24,12.3 38.73,12.3 39.52,11.5 39.52,10.63 38.65,9.76 X10.5
TW  (via drill 0.3)
  Top 0.152: IC8.12 33.78,22.96 34.44,22.3 v34.68,22.3
  Bottom 0.152: v34.68,22.3 33.89,22.3 33.25,21.66 33.25,15.71 35.71,13.25 39.21,13.25 41.83,10.63 41.83,9.84 42.78,8.88 44.21,8.88 44.76,9.44 54.76,9.44 55.24,9.92 55.24,11.9 X8.8 | X8.8
TXD
  Top 0.152: IC8.10 35.55,24.68 35.55,23.73 35.16,23.33 34.52,23.33 32.3,25.55 32.3,26.03 31.35,26.98 30.32,26.98 29.28,28.01 25.87,28.01 U1.5
  Top 0.305: U1.5 24.8,28.05 24.44,28.41 22.22,28.41 21.58,27.77 21.58,24.6 20.31,23.33 20.31,17.3 18.73,15.71 IC9.11 16.5,15.71 | IC8.10 35.48,24.68 35.55,24.6
VCC  (via drill 0.3)
  Top 0.305: C27.2 29.36,14.68 28.33,15.71 28.33,20.47 28.33,20.55
  Top 0.356: U1.4 22.59,27.4 arc-90 v22.54,27.46
  Top 0.406: U1.20 19.7,30.65 20,30.95 22.46,30.95 | v22.54,27.46 22.59,27.4 | L1.1 41.88,8.75 42.46,8.17 42.46,6.5 41.19,5.23 X10.4 | C27.2 | R58.1 29.84,9.38 29.84,2.38 | v22.54,30.95 22.46,30.95 | 22.46,30.95 22.54,31.03 | 30.47,20.47 30.47,22.38 C24.+ | IC9.16 15.31,9.36 15.08,9.12 15.08,6.34 C30.+
  Top 0.508: IC9.16 20,9.36 20.95,10.31 20.95,16.03 24.12,19.2 C25.1 C26.1 28.33,20.47 30.47,20.47 30.47,19.52 31.03,18.96 IC8.17 34.13,18.96 35.16,18.96 | 44.37,18.16 IC8.38 46.04,18.16 47.78,16.42 60.32,16.42 60.32,16.98 60.74,17.38 | IC8.5 39.45,23.65 38.89,23.09 36.75,23.09 36.75,20.63 36.75,20.55 35.16,18.96 | 35.16,18.96 | X7.11 61.59,18.24 | 41.19,2.38 X10.4
  Top 0.61: C30.+ 17.14,2.38 29.84,2.38 41.19,2.38 52.06,2.38 56.91,2.38 63.26,2.38 63.26,13.17 | X7.11 60.32,16.98 60.32,16.42 60.32,14.44 X8.12 63.26,13.17 | 60.74,17.38 61.59,18.24 | 35.79,36.59 25.16,36.59 22.54,33.97 22.54,31.03 | 63.26,13.17 | C12.+ 62.46,43.65 50.32,43.65 49.72,44.24 | IC4.3 49.63,44.34 49.72,44.24 | 49.72,44.24 49.21,43.73 48.18,43.73 46.98,42.54 C16.2 C18.2 42.14,41.43 41.51,40.79 41.51,37.78 40.32,36.59 37.14,36.59 | 37.14,36.59 | C20.2 37.14,36.59 | 35.79,36.59 37.14,36.59 | 35.79,36.59
  Top 0.813: X8.12
  Bottom 0.406: X10.7 37.38,5.95 39.92,5.95 X10.4
  Bottom 0.61: 22.54,27.54 v22.54,30.95 | C30.+ 15.39,6.03 15.39,10.07 14.92,10.55 14.92,23.89 16.66,25.63 20.63,25.63 22.54,27.54 | 22.54,27.54 v22.54,27.46
VDD  (via drill 0.5, 0.6)
  Top 0.406: IC4.1 54.19,48.47 v54.84,49.13 | IC5.IN | D8.- 53.02,52.78 IC5.IN | D8.- 57.01,55.66 58.41,57.06 C17.+ | C17.+ | D8.- 50.34,58.33 47.54,58.33 46.43,59.45 46.43,61.35 48.49,63.41 48.89,63.41 | D4.- 49.21,90.09 49.21,90.08 49.21,91.83 48.89,92.15 K1.1 47.46,93.26 | 48.89,63.41 K2.1 | K2.1 | D9.- 48.89,68.47 48.89,63.41 | 47.46,93.26 | v44.68,89.45 44.68,90.48 47.46,93.26
  Bottom 0.406: IC5.IN | v54.84,49.13 54.84,50.95 IC5.IN | 48.89,63.41 | K2.1 48.89,63.41 | v44.68,89.45 44.68,79.84 43.25,78.42 43.25,76.83 44.68,75.4 44.68,67.62 48.89,63.41
VPP  (via drill 0.5)
  Top 0.406: R52.1 56.23,25.83 56.91,26.5 57.94,26.5 58.73,27.3 63.73,27.3 64.69,28.25 v64.69,31.27 | R28.1 64.53,66.03 67.15,63.41 68.81,63.41 68.82,63.41 K2.COM | X2.1 v64.69,49.52 | X2.1 | R1.1 64.53,90.88 66.9,93.25 K1.COM
  Top 1.422: K2.COM 71.46,60.8 73.73,60.8 77.54,56.98 X2.1 | X2.1 | X2.1
  Bottom 0.406: v64.69,31.27 v64.69,49.52
  Bottom 1.422: K1.COM 68.81,78.02 68.81,63.41 K2.COM
VPP1
  Top 0.406: K1.NO 70.16,90.64 | 70.16,90.64 C1.1 | R12.2 70.4,87.94 70.16,88.18 70.16,90.64
  Bottom 1.422: K1.NO 72.79,89.76 75.8,86.75 X1.3 | X1.3
W1  (via drill 0.3)
  Top 0.152: IC8.19 32.94,17.3 33.25,17.3 33.17,17.3 v34.36,17.3
  Bottom 0.152: v34.36,17.3 35,16.66 35,15.23 36.11,14.12 39.68,14.12 42.7,11.11 42.7,10.23 43.1,9.84 43.81,9.84 44.29,10.31 44.29,11.58 44.84,12.14 50.4,12.14 X8.4 | X8.4
W2  (via drill 0.3)
  Top 0.152: IC8.20 32.87,16.58 33.81,16.58 34.28,16.11 v34.36,16.11
  Bottom 0.152: v34.36,16.11 34.36,15.23 35.95,13.65 39.44,13.65 42.3,10.79 42.3,10.07 43.02,9.36 43.81,9.36 44.68,10.23 44.68,11.34 45.08,11.74 52.54,11.74 X8.6 | X8.6

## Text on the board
tPlace: V | 1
